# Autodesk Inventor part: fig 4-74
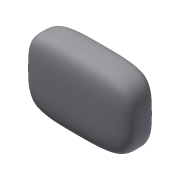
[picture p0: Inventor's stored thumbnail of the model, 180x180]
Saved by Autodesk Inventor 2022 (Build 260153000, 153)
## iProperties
Created: 2012-07
Part Number: fig 4-74
Material: Generic
Document SubType Name: Modeling
Designer: CADCIM
Density: 1 g/cm^3
Appearance: Default
Author: CADCIM
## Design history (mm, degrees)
feature "Form1"
body "Solid1"
body "Solid2"
